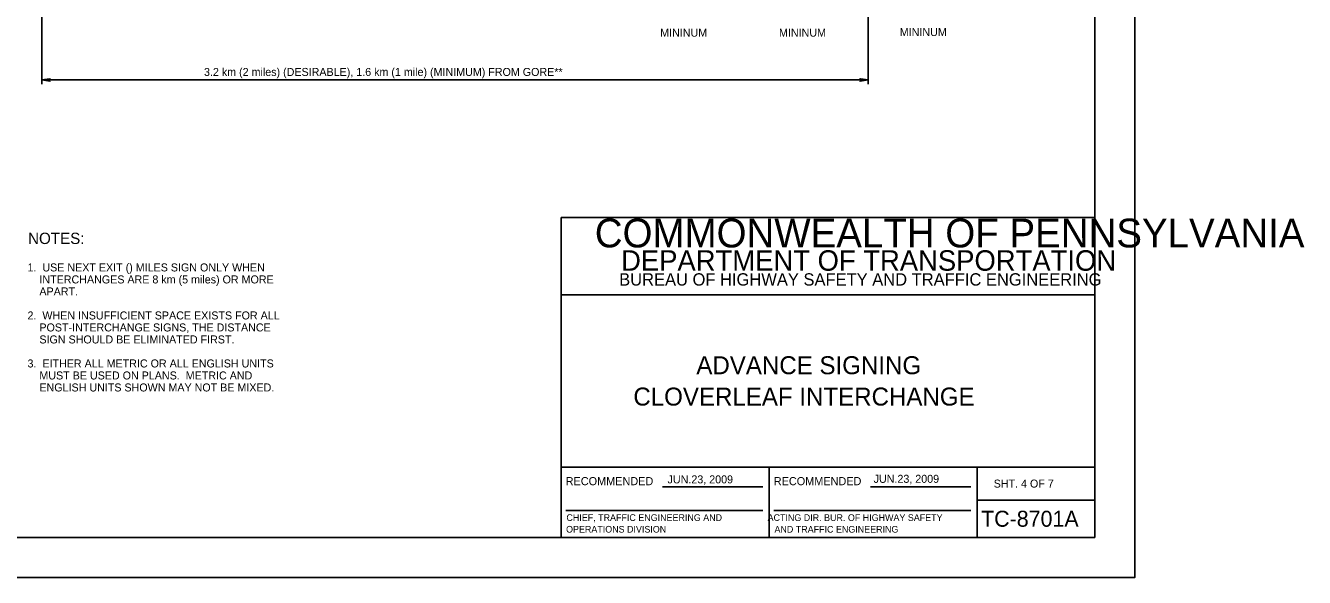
# Model space of a CAD drawing. Extents: x 640994 to 644422, y 298458 to 299646.
# Drawn here: x 643942.6 to 644421.9, y 299051.6 to 299258.5 of the extents above; entities that cross this region are included whole.
import ezdxf

# ---------------------------------------------------------------- set-up
doc = ezdxf.new("R2010")
doc.units = 0
for name, color, linetype in [('1', 7, 'Continuous'), ('2', 7, 'Continuous'), ('PLT-BNDY', 7, 'Continuous'), ('XCS-GRID-MIN', 7, 'Continuous')]:
    doc.layers.add(name, color=color, linetype=linetype)

msp = doc.modelspace()

# ---------------------------------------------------------------- linework, layer by layer
at = {"layer": '1'}
for p, q in [((644343.31, 299066.63), (644343.31, 299630.63)), ((644143.31, 299066.63), (644143.31, 299186.63)), ((644143.31, 299186.63), (644343.31, 299186.63)), ((644343.31, 299157.63), (644143.31, 299157.63)), ((644143.31, 299093), (644343.31, 299093)), ((644221.31, 299093), (644221.31, 299066.63)), ((644299.19, 299066.63), (644299.19, 299093)), ((644181.24, 299085.57), (644218.87, 299085.57)), ((644259.24, 299085.57), (644296.87, 299085.57)), ((644299.19, 299080.63), (644343.31, 299080.63)), ((644144.99, 299076.68), (644218.87, 299076.68)), ((644222.99, 299076.68), (644296.87, 299076.68)), ((644343.31, 299066.63), (643557.31, 299066.63)), ((643557.31, 299066.63), (644143.31, 299066.63))]:
    msp.add_line(p, q, dxfattribs=at)
at = {"layer": '2'}
for p, q in [((644258.31, 299314.64), (644258.31, 299236.52)), ((643948.69, 299311.52), (643948.69, 299236.52)), ((643948.69, 299238.14), (644258.31, 299238.14))]:
    msp.add_line(p, q, dxfattribs=at)
for points in [[(643951.54, 299237.78), (643951.43, 299237.99), (643948.69, 299238.14), (643951.54, 299237.78), (643951.69, 299237.66), (643948.69, 299238.14), (643951.43, 299238.28), (643951.53, 299238.48), (643948.69, 299238.14), (643951.69, 299238.62), (643951.53, 299238.48)], [(644255.46, 299238.5), (644255.56, 299238.29), (644258.31, 299238.14), (644255.46, 299238.5), (644255.31, 299238.62), (644258.31, 299238.14), (644255.57, 299238.01), (644255.47, 299237.8), (644258.31, 299238.14), (644255.31, 299237.66), (644255.47, 299237.8)]]:
    msp.add_lwpolyline(points, dxfattribs=at)
at = {"layer": 'XCS-GRID-MIN'}
msp.add_lwpolyline([(643517.31, 299645.63), (644358.31, 299645.63), (644358.31, 299051.63), (643517.31, 299051.63)], close=True, dxfattribs=at)

# ---------------------------------------------------------------- texts
at = {"layer": '1'}
for s, height, p in [('COMMONWEALTH OF PENNSYLVANIA', 10.7828, (644155.9, 299175.36)), ('DEPARTMENT OF TRANSPORTATION', 7.6837, (644165.76, 299166.61)), ('BUREAU OF HIGHWAY SAFETY AND TRAFFIC ENGINEERING', 4.6253, (644165.04, 299161.04)), ('ADVANCE SIGNING', 6.75, (644193.96, 299127.81)), ('CLOVERLEAF INTERCHANGE', 6.75, (644170.36, 299116.06)), ('RECOMMENDED', 3.048, (644144.99, 299086.2)), ('RECOMMENDED', 3.048, (644222.99, 299086.2)), ('SHT. 4 OF 7', 3, (644305.4, 299085.31)), ('TC-8701A', 6, (644300.68, 299070.63))]:
    msp.add_text(s, height=height, dxfattribs=at).set_placement(p)
at = {"layer": '2'}
for s, height, p in [(' MININUM', 3, (644179.3, 299254.36)), (' MININUM', 3, (644223.83, 299254.36)), (' MININUM', 3, (644269.09, 299254.6)), ('3.2 km (2 miles) (DESIRABLE), 1.6 km (1 mile) (MINIMUM) FROM GORE**', 3, (644009.44, 299239.64)), ('NOTES:', 4.25, (643943.5, 299176.63)), ('1.  USE NEXT EXIT () MILES SIGN ONLY WHEN', 3, (643943.29, 299166.35)), ('    INTERCHANGES ARE 8 km (5 miles) OR MORE', 3, (643943.29, 299161.85)), ('    APART.', 3, (643943.29, 299157.35)), ('2.  WHEN INSUFFICIENT SPACE EXISTS FOR ALL', 3, (643943.29, 299148.35)), ('    POST-INTERCHANGE SIGNS, THE DISTANCE', 3, (643943.29, 299143.85)), ('    SIGN SHOULD BE ELIMINATED FIRST.', 3, (643943.29, 299139.35)), ('3.  EITHER ALL METRIC OR ALL ENGLISH UNITS', 3, (643943.29, 299130.35)), ('    MUST BE USED ON PLANS.  METRIC AND', 3, (643943.29, 299125.85)), ('    ENGLISH UNITS SHOWN MAY NOT BE MIXED.', 3, (643943.29, 299121.35)), ('JUN.23, 2009', 3, (644183.18, 299086.89)), ('JUN.23, 2009', 3, (644260.41, 299087.1))]:
    msp.add_text(s, height=height, dxfattribs=at).set_placement(p)
at = {"layer": 'PLT-BNDY'}
for s, p in [('CHIEF, TRAFFIC ENGINEERING AND', (644145.28, 299072.81)), ('  ACTING DIR. BUR. OF HIGHWAY SAFETY', (644218.81, 299072.8)), ('  ACTING DIR. BUR. OF HIGHWAY SAFETY', (644218.81, 299072.8)), ('OPERATIONS DIVISION', (644145.14, 299068.44))]:
    msp.add_text(s, height=2.5, dxfattribs=at).set_placement(p)
msp.add_text('AND TRAFFIC ENGINEERING', height=2.5, rotation=360, dxfattribs=at).set_placement((644223.25, 299068.43))
msp.add_text('AND TRAFFIC ENGINEERING', height=2.5, rotation=360, dxfattribs=at).set_placement((644223.25, 299068.43))

doc.saveas('drawing.dxf')
